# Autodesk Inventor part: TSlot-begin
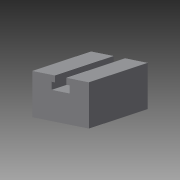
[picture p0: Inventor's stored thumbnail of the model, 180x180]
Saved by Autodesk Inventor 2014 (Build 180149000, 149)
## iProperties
Created: 2008-06
Part Number: TSlot-begin
Document SubType Name: Modeling
Designer: Autodesk
Density: 1 g/cm^3
Material: Generic
Appearance: Default
Author: Autodesk
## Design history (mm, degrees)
sketch "Sketch1"
  geometry: L1 (-30, 0)-(30, 0); L2 (30, 0)-(30, 40); L3 (30, 40)-(-30, 40); L4 (-30, 40)-(-30, 0); 1 further point
  constraints: 8 end point, 2 parallel, 1 horizontal, 1 midpoint, 1 perpendicular
  dimensions: "d10" = 60 distance of L2.end L3.end; "d11" = 30 distance from line of point (0, 0) L4; "d12" = 40 distance of L3.end L1.start
extrude "Extrusion1" new body sketch "Sketch1" stored distance "d0" = 80; taper "d1" = 0 deg
sketch "Sketch2"
  geometry: L1 (-6, 40)-(6, 40); L2 (6, 40)-(6, 34); L3 (-6, 34)-(-6, 40); L4 (9.5, 34)-(9.5, 27); L5 (9.5, 27)-(-9.5, 27); L6 (-9.5, 27)-(-9.5, 34); L7 (-9.5, 34)-(-6, 34); L8 (6, 34)-(9.5, 34); L9 (0, 46)-(0, 11); L10 (-30, 40)-(30, 40) reference
  constraints: 18 end point, 4 parallel, 4 perpendicular, 3 horizontal, 2 collinear
  dimensions: "d2" = 12 distance between parallel lines of L2 L3; "d3" = 6 distance between parallel lines of L9 L3 (= 0.5 x d2); "d4" = 19 distance of L4.end L5.end; "d5" = 9.5 distance between parallel lines of L9 L6 (= 0.5 x d4); "d6" = 13 distance between parallel lines of L5 L1; "d7" = 7 distance of L4.start L4.end
extrude "Extrusion2" cut sketch "Sketch2" stored distance "d8" = 80; taper "d9" = 0 deg
body "Solid1"
